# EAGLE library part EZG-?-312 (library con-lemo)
LEMO Connector Source: http://www.lemo.com/pdfs/catalog/ROW/German/unipole_multipole.pdf
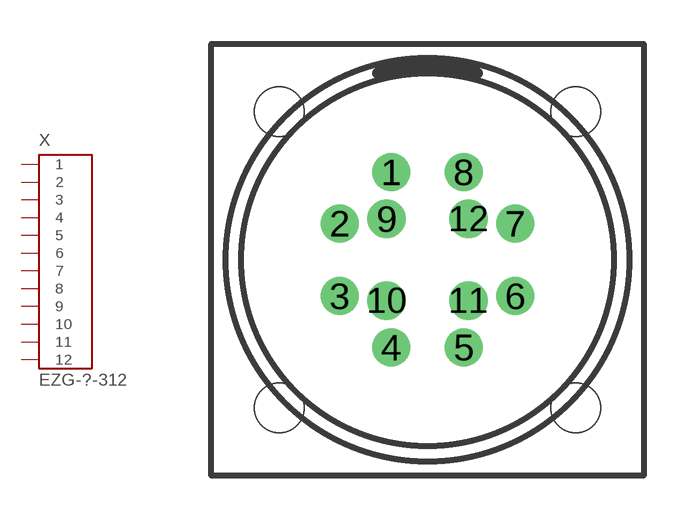
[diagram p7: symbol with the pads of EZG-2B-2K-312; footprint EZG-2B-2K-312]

Designator prefix X

## EZG-2B-312 (OC_FARNELL: unknown; OC_NEWARK: unknown)  [EZG-2B-2K-312]
1  1  pas
2  2  pas
3  3  pas
4  4  pas
5  5  pas
6  6  pas
7  7  pas
8  8  pas
9  9  pas
10  10  pas
11  11  pas
12  12  pas

## EZG-2K-312 (OC_FARNELL: unknown; OC_NEWARK: unknown)  [EZG-2B-2K-312]
Pads as for EZG-2B-2K-312

## Footprint EZG-2B-2K-312 (pad centres in mm)
LEMO Connector Source: http://www.lemo.com/pdfs/catalog/ROW/German/unipole_multipole.pdf
drill 0.8 pad 1.3 round: 1 -1.244,3.002; 2 -3.002,1.244; 3 -3.002,-1.244; 4 -1.244,-3.002; 5 1.244,-3.002; 6 3.002,-1.244; 7 3.002,1.244; 8 1.244,3.002; 9 -1.4,1.4; 10 -1.4,-1.4; 11 1.4,-1.4; 12 1.4,1.4
hole 1.7 at -5.08,5.08
hole 1.7 at 5.08,5.08
hole 1.7 at 5.08,-5.08
hole 1.7 at -5.08,-5.08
